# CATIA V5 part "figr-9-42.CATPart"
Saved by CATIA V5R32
Part number: Part1
Bounding box of the stored display mesh (mm): x -60 to 60, y -70.383 to 65.913, z 0 to 125
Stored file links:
  D:\PROJECTS\Project 2022\CATIA V5 6R 2022\Resources\Part Files\c09_catia_v5_6r2022_prt\c09_catia_v5_6r2022_prt\figr-9-42.CATPart
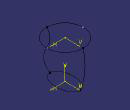
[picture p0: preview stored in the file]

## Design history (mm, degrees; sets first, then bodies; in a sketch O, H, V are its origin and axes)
Set1
  Plane1: type Offset, RefPlane xy-plane, Offset 125
Body1 (main body)
  Sketch1 on xy-plane, origin (0, 0, 0), H (1, 0, 0), V (0, 1, 0)
    ellipse A1 centre (0, 0) semi-axes 50, 30 rotation 270
    point P1 (30, 0)
    coincidence: P1 H, A1 P1
  Sketch2 on Plane1, origin (0, 0, 125), H (1, 0, 0), V (0, 1, 0)
    circle A1 centre (0, 0) radius 60
  Sketch3 on yz-plane, origin (0, 0, 0), H (0, 1, 0), V (0, 0, 1)
    arc A1 centre (-129.6632, 77.2731) radius 195.5761 from (50, 0) to (60, 125) ccw
    point P2 (50, 0)
    point P3 (60, 125)
    reference projected line E1 (-50, 0) -> (50, 0) from edge of Sketch1
    reference projected line E2 (-60, 125) -> (60, 125) from edge of Sketch2
    coincidence: P2 H, P2 E1, P3 E2
  Sketch4 on yz-plane, origin (0, 0, 0), H (0, 1, 0), V (0, 0, 1)
    spline S1 through (-50, 0) (-70, 40) (-50, 100) (-60, 125)
    reference projected line E1 (-60, 125) -> (60, 125) from edge of Sketch2
    reference projected line E2 (-50, 0) -> (50, 0) from edge of Sketch1
    point P1 (-60, 125)
    point P2 (-50, 0)
    coincidence: P1 E1, P2 E2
